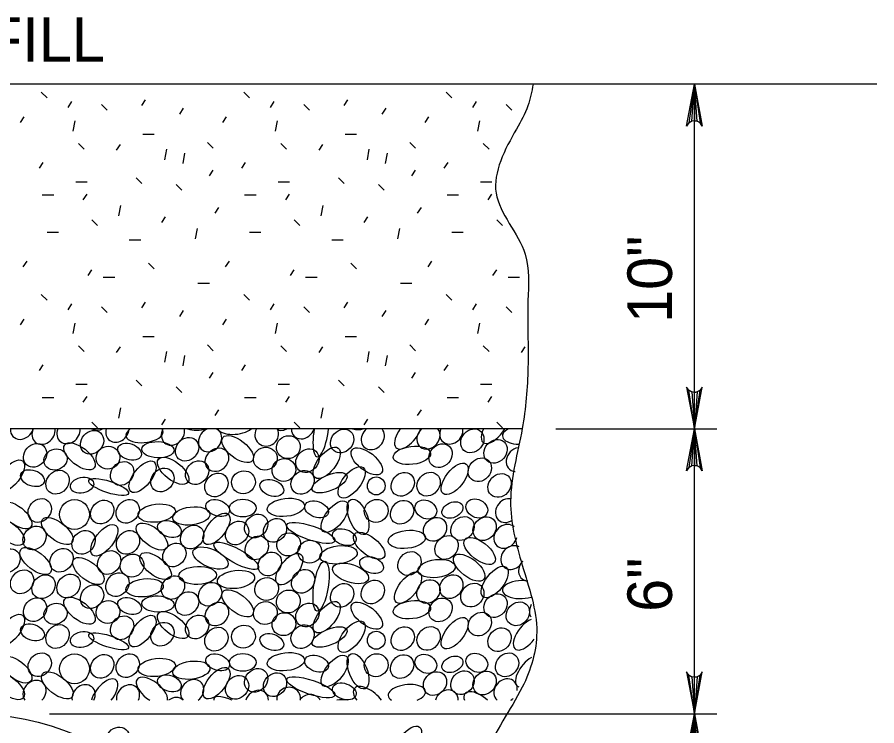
# Model space of a CAD drawing. Extents: x 1.32 to 7.47, y -3.56 to 5.14.
# Drawn here: x 3.909 to 5.068, y 0.019 to 0.974 of the extents above; entities that cross this region are included whole.
import ezdxf

# ---------------------------------------------------------------- set-up
doc = ezdxf.new("R2010")
doc.units = 0
for name, color, linetype in [('DETL-DIMS', 7, 'Continuous'), ('DETL-LINE', 7, 'Continuous'), ('DETL-NOTE', 7, 'Continuous'), ('DETL-PATT', 7, 'Continuous')]:
    doc.layers.add(name, color=color, linetype=linetype)

msp = doc.modelspace()

# ---------------------------------------------------------------- linework, layer by layer
at = {"layer": 'DETL-DIMS'}
for p, q in [((4.8221, 0.4194), (4.8221, 0.8841)), ((4.6354, 0.4194), (4.8524, 0.4194)), ((4.8221, 0.0356), (4.8221, 0.4194)), ((3.9532, 0.0356), (4.8524, 0.0356)), ((4.8221, -0.6917), (4.8221, 0.0356))]:
    msp.add_line(p, q, dxfattribs=at)
for points in [[(4.8221, 0.8841), (4.8327, 0.8276), (4.8297, 0.832), (4.8259, 0.8342), (4.8221, 0.8349), (4.8184, 0.8342), (4.8146, 0.832), (4.8116, 0.8276), (4.8221, 0.8841), (4.8146, 0.832), (4.8184, 0.8342), (4.8221, 0.8841), (4.8221, 0.8349), (4.8259, 0.8342), (4.8221, 0.8841), (4.8297, 0.832)], [(4.8221, 0.4194), (4.8327, 0.4759), (4.8297, 0.4716), (4.8259, 0.4693), (4.8221, 0.4687), (4.8184, 0.4693), (4.8146, 0.4716), (4.8116, 0.4759), (4.8221, 0.4194), (4.8146, 0.4716), (4.8184, 0.4693), (4.8221, 0.4194), (4.8221, 0.4687), (4.8259, 0.4693), (4.8221, 0.4194), (4.8297, 0.4716)], [(4.8221, 0.4194), (4.8327, 0.363), (4.8297, 0.3673), (4.8259, 0.3696), (4.8221, 0.3702), (4.8184, 0.3696), (4.8146, 0.3673), (4.8116, 0.363), (4.8221, 0.4194), (4.8146, 0.3673), (4.8184, 0.3696), (4.8221, 0.4194), (4.8221, 0.3702), (4.8259, 0.3696), (4.8221, 0.4194), (4.8297, 0.3673)], [(4.8221, 0.0356), (4.8327, 0.0921), (4.8297, 0.0877), (4.8259, 0.0855), (4.8221, 0.0849), (4.8184, 0.0855), (4.8146, 0.0877), (4.8116, 0.0921), (4.8221, 0.0356), (4.8146, 0.0877), (4.8184, 0.0855), (4.8221, 0.0356), (4.8221, 0.0849), (4.8259, 0.0855), (4.8221, 0.0356), (4.8297, 0.0877)], [(4.8221, 0.0356), (4.8327, -0.0209), (4.8297, -0.0165), (4.8259, -0.0143), (4.8221, -0.0136), (4.8184, -0.0143), (4.8146, -0.0165), (4.8116, -0.0209), (4.8221, 0.0356), (4.8146, -0.0165), (4.8184, -0.0143), (4.8221, 0.0356), (4.8221, -0.0136), (4.8259, -0.0143), (4.8221, 0.0356), (4.8297, -0.0165)]]:
    msp.add_lwpolyline(points, dxfattribs=at)
at = {"layer": 'DETL-LINE'}
for p, q in [((5.0678, 0.8841), (2.3812, 0.8841)), ((4.59, 0.4194), (3.0905, 0.4194))]:
    msp.add_line(p, q, dxfattribs=at)
msp.add_circle((3.8471, -0.328), 0.3636, dxfattribs=at)
msp.add_spline([(4.6047, 0.8841), (4.5978, 0.8549), (4.5822, 0.8236), (4.5548, 0.7374), (4.5939, 0.6551), (4.5978, 0.5924), (4.5978, 0.5022), (4.59, 0.4199), (4.5744, 0.322), (4.59, 0.2357), (4.6096, 0.1456), (4.59, 0.0712), (4.543, -0.019), (4.5665, -0.1679), (4.5783, -0.2463), (4.5509, -0.3207), (4.5626, -0.4069), (4.6057, -0.5167), (4.5978, -0.599), (4.5704, -0.6812), (4.5626, -0.7518), (4.59, -0.8615), (4.5822, -0.8733), (4.5744, -0.9341)], degree=3, dxfattribs=at)
at = {"layer": 'DETL-PATT'}
for p, q in [((3.942, 0.8734), (3.9497, 0.8657)), ((4.2148, 0.8734), (4.2225, 0.8657)), ((4.4875, 0.8734), (4.4952, 0.8657)), ((3.978, 0.8529), (3.9831, 0.8606)), ((4.0773, 0.8555), (4.0825, 0.8632)), ((4.2507, 0.8529), (4.2559, 0.8606)), ((4.3501, 0.8555), (4.3552, 0.8632)), ((4.5235, 0.8529), (4.5286, 0.8606)), ((4.0229, 0.8568), (4.0306, 0.8491)), ((4.1287, 0.8439), (4.1338, 0.8516)), ((4.2957, 0.8568), (4.3034, 0.8491)), ((4.4014, 0.8439), (4.4066, 0.8516)), ((4.5684, 0.8568), (4.5761, 0.8491)), ((3.9138, 0.8324), (3.9189, 0.8401)), ((3.987, 0.8349), (3.9844, 0.8208)), ((4.1865, 0.8324), (4.1916, 0.8401)), ((4.2597, 0.8349), (4.2571, 0.8208)), ((4.4592, 0.8324), (4.4644, 0.8401)), ((4.5324, 0.8349), (4.5299, 0.8208)), ((4.0786, 0.8169), (4.094, 0.8169)), ((4.3514, 0.8169), (4.3668, 0.8169)), ((3.9921, 0.8041), (3.9998, 0.7964)), ((4.0435, 0.7951), (4.0486, 0.8028)), ((4.166, 0.8054), (4.1737, 0.7977)), ((4.2648, 0.8041), (4.2726, 0.7964)), ((4.3162, 0.7951), (4.3214, 0.8028)), ((4.4387, 0.8054), (4.4464, 0.7977)), ((4.5376, 0.8041), (4.5453, 0.7964)), ((4.1107, 0.7964), (4.1082, 0.7823)), ((4.1351, 0.7913), (4.1326, 0.7771)), ((4.3835, 0.7964), (4.3809, 0.7823)), ((4.4079, 0.7913), (4.4053, 0.7771)), ((3.9395, 0.7707), (3.9446, 0.7784)), ((4.2122, 0.7707), (4.2173, 0.7784)), ((4.4849, 0.7707), (4.4901, 0.7784)), ((4.1685, 0.7604), (4.1737, 0.7682)), ((4.4413, 0.7604), (4.4464, 0.7682)), ((4.0696, 0.7579), (4.0773, 0.7502)), ((4.3424, 0.7579), (4.3501, 0.7502)), ((3.9883, 0.7527), (4.0037, 0.7527)), ((4.1236, 0.7489), (4.1313, 0.7412)), ((4.261, 0.7527), (4.2764, 0.7527)), ((4.3963, 0.7489), (4.404, 0.7412)), ((4.5337, 0.7527), (4.5491, 0.7527)), ((3.9433, 0.7348), (3.9587, 0.7348)), ((3.9985, 0.7283), (4.0037, 0.736)), ((4.216, 0.7348), (4.2315, 0.7348)), ((4.2713, 0.7283), (4.2764, 0.736)), ((4.4888, 0.7348), (4.5042, 0.7348)), ((4.544, 0.7283), (4.5491, 0.736)), ((4.0486, 0.7206), (4.0461, 0.7065)), ((4.3214, 0.7206), (4.3188, 0.7065)), ((4.1762, 0.7103), (4.1814, 0.7181)), ((4.449, 0.7103), (4.4541, 0.7181)), ((4.0101, 0.7014), (4.0178, 0.6937)), ((4.1043, 0.6975), (4.1095, 0.7052)), ((4.2828, 0.7014), (4.2905, 0.6937)), ((4.377, 0.6975), (4.3822, 0.7052)), ((4.5556, 0.7014), (4.5633, 0.6937)), ((3.9497, 0.6847), (3.9651, 0.6847)), ((4.1518, 0.6898), (4.1493, 0.6757)), ((4.2225, 0.6847), (4.2379, 0.6847)), ((4.4246, 0.6898), (4.422, 0.6757)), ((4.4952, 0.6847), (4.5106, 0.6847)), ((4.0606, 0.6744), (4.0761, 0.6744)), ((4.3334, 0.6744), (4.3488, 0.6744)), ((3.9176, 0.638), (3.9228, 0.6457)), ((4.0863, 0.6431), (4.094, 0.6354)), ((4.1904, 0.638), (4.1955, 0.6457)), ((4.3591, 0.6431), (4.3668, 0.6354)), ((4.4631, 0.638), (4.4682, 0.6457)), ((4.005, 0.6264), (4.0101, 0.6341)), ((4.2777, 0.6264), (4.2828, 0.6341)), ((4.5504, 0.6264), (4.5556, 0.6341)), ((4.0255, 0.6238), (4.0409, 0.6238)), ((4.1531, 0.6161), (4.1685, 0.6161)), ((4.2982, 0.6238), (4.3136, 0.6238)), ((4.4258, 0.6161), (4.4413, 0.6161)), ((4.571, 0.6238), (4.5864, 0.6238)), ((3.942, 0.6007), (3.9497, 0.593)), ((4.2148, 0.6007), (4.2225, 0.593)), ((4.4875, 0.6007), (4.4952, 0.593)), ((3.978, 0.5802), (3.9831, 0.5879)), ((4.0229, 0.584), (4.0306, 0.5763)), ((4.0773, 0.5827), (4.0825, 0.5905)), ((4.2507, 0.5802), (4.2559, 0.5879)), ((4.2957, 0.584), (4.3034, 0.5763)), ((4.3501, 0.5827), (4.3552, 0.5905)), ((4.5235, 0.5802), (4.5286, 0.5879)), ((4.5684, 0.584), (4.5761, 0.5763)), ((4.1287, 0.5712), (4.1338, 0.5789)), ((4.4014, 0.5712), (4.4066, 0.5789)), ((3.9138, 0.5596), (3.9189, 0.5673)), ((3.987, 0.5622), (3.9844, 0.5481)), ((4.1865, 0.5596), (4.1916, 0.5673)), ((4.2597, 0.5622), (4.2571, 0.5481)), ((4.4592, 0.5596), (4.4644, 0.5673)), ((4.5324, 0.5622), (4.5299, 0.5481)), ((4.0786, 0.5442), (4.094, 0.5442)), ((4.3514, 0.5442), (4.3668, 0.5442)), ((3.9921, 0.5314), (3.9998, 0.5237)), ((4.0435, 0.5224), (4.0486, 0.5301)), ((4.1107, 0.5237), (4.1082, 0.5095)), ((4.166, 0.5327), (4.1737, 0.5249)), ((4.2648, 0.5314), (4.2726, 0.5237)), ((4.3162, 0.5224), (4.3214, 0.5301)), ((4.3835, 0.5237), (4.3809, 0.5095)), ((4.4387, 0.5327), (4.4464, 0.5249)), ((4.5376, 0.5314), (4.5453, 0.5237)), ((4.589, 0.5224), (4.5941, 0.5301)), ((4.1351, 0.5185), (4.1326, 0.5044)), ((4.4079, 0.5185), (4.4053, 0.5044)), ((3.9395, 0.498), (3.9446, 0.5057)), ((4.2122, 0.498), (4.2173, 0.5057)), ((4.4849, 0.498), (4.4901, 0.5057)), ((4.1685, 0.4877), (4.1737, 0.4954)), ((4.4413, 0.4877), (4.4464, 0.4954)), ((3.9883, 0.48), (4.0037, 0.48)), ((4.0696, 0.4851), (4.0773, 0.4774)), ((4.1236, 0.4762), (4.1313, 0.4684)), ((4.261, 0.48), (4.2764, 0.48)), ((4.3424, 0.4851), (4.3501, 0.4774)), ((4.3963, 0.4762), (4.404, 0.4684)), ((4.5337, 0.48), (4.5491, 0.48)), ((3.9433, 0.462), (3.9587, 0.462)), ((3.9985, 0.4556), (4.0037, 0.4633)), ((4.216, 0.462), (4.2315, 0.462)), ((4.2713, 0.4556), (4.2764, 0.4633)), ((4.4888, 0.462), (4.5042, 0.462)), ((4.544, 0.4556), (4.5491, 0.4633)), ((4.0486, 0.4479), (4.0461, 0.4338)), ((4.1762, 0.4376), (4.1814, 0.4453)), ((4.3214, 0.4479), (4.3188, 0.4338)), ((4.449, 0.4376), (4.4541, 0.4453)), ((4.0101, 0.4286), (4.0178, 0.4209)), ((4.1043, 0.4248), (4.1095, 0.4325)), ((4.2828, 0.4286), (4.2905, 0.4209)), ((4.377, 0.4248), (4.3822, 0.4325)), ((4.5556, 0.4286), (4.5633, 0.4209))]:
    msp.add_line(p, q, dxfattribs=at)
for centre in [(3.9868, 0.3041), (3.9868, 0.0961)]:
    msp.add_circle(centre, 0.0201, dxfattribs=at)
for centre, major_axis, ratio, start_param, end_param in [((3.916, 0.4214), (0.0114, 0.0128), 0.844245, 2.337239, 5.2336), ((3.945, 0.4148), (0.0114, 0.0128), 0.844245, 1.920061, 5.650779), ((3.9787, 0.4157), (0.0114, 0.0128), 0.844245, 1.977863, 5.592976), ((4.0054, 0.4359), (-0.0199, 0.0156), 0.479042, 2.140528, 3.0476), ((4.0446, 0.4176), (0.0114, 0.0128), 0.844245, 2.101903, 5.468936), ((4.0811, 0.4133), (-0.0251, -0.003), 0.479042, 5.523456, 9.693542), ((4.1194, 0.4136), (0.0114, 0.0128), 0.844245, 1.843624, 5.727215), ((4.1527, 0.43), (-0.0253, -0.0008), 0.479042, 0.985107, 2.022292), ((4.1694, 0.4047), (0.0114, 0.0128), 0.844245, 1.036345, 6.534494), ((4.2043, 0.4245), (-0.0251, -0.003), 0.479042, 0.177054, 2.473573), ((4.2457, 0.4118), (0.015, 0.006), 0.948581, 2.223153, 6.403606), ((4.2762, 0.4384), (-0.0156, -0.0199), 0.479042, 6.174501, 7.111824), ((4.2947, 0.4221), (0.0114, 0.0128), 0.844245, 2.382235, 5.188604), ((4.3189, 0.4156), (0.0052, 0.0337), 0.282192, 1.499195, 4.870192), ((4.3587, 0.4326), (-0.024, 0.0079), 0.479042, 1.837904, 2.504279), ((4.3887, 0.4076), (0.0114, 0.0128), 0.844245, 1.383909, 6.18693), ((4.4362, 0.4136), (-0.0156, -0.0199), 0.479042, 4.793971, 8.492354), ((4.4636, 0.4083), (0.0114, 0.0128), 0.844245, 1.442961, 6.127878), ((4.4945, 0.415), (0.0114, 0.0128), 0.844245, 1.933643, 5.637196), ((4.553, 0.4211), (-0.0156, -0.0199), 0.479042, 5.151093, 8.135232), ((4.5887, 0.4109), (-0.0253, -0.0008), 0.479042, 5.437186, 7.710822), ((4.5841, 0.3782), (0.0114, 0.0128), 0.844245, 0.789884, 3.730487), ((4.5696, 0.3094), (0.0114, 0.0128), 0.844245, 0.446616, 4.424977), ((4.5676, 0.2747), (0.0114, 0.0128), 0.844245, 6.263167, 11.550365), ((4.5768, 0.2461), (0.0114, 0.0128), 0.844245, 0.181002, 5.06616), ((4.6007, 0.2307), (0.0114, 0.0128), 0.844245, 1.485719, 3.761443), ((4.5887, 0.2029), (-0.0253, -0.0008), 0.479042, 4.32869, 8.397006), ((4.6179, 0.1858), (-0.0156, -0.0199), 0.479042, 5.210525, 6.260787), ((4.5962, 0.1427), (-0.0156, -0.0199), 0.479042, 3.841705, 7.893613), ((4.5992, 0.0926), (-0.0156, -0.0199), 0.479042, 3.986958, 6.45917), ((3.9329, 0.0645), (0.0114, 0.0128), 0.844245, 4.624083, 9.229941), ((4.0269, 0.0614), (-0.0156, -0.0199), 0.479042, 1.564537, 5.438603), ((4.0911, 0.0665), (-0.0199, 0.0156), 0.479042, 3.399625, 8.071688), ((4.1452, 0.0657), (0.0114, 0.0128), 0.844245, 4.512207, 9.341818), ((4.5676, 0.0667), (0.0114, 0.0128), 0.844245, 5.372018, 9.43564), ((3.9989, 0.0587), (0.0114, 0.0128), 0.844245, 5.042086, 8.811939), ((4.0588, 0.0586), (0.0114, 0.0128), 0.844245, 5.05265, 8.801375), ((4.2753, 0.0558), (0.015, 0.006), 0.948581, 5.750872, 9.159072), ((4.3837, 0.054), (-0.0199, 0.0156), 0.479042, 4.150915, 7.320397), ((4.4345, 0.0627), (-0.0251, -0.003), 0.479042, 2.09792, 6.835893), ((4.1213, 0.0415), (0.0114, 0.0128), 0.844245, 6.230995, 7.623029), ((4.2046, 0.0404), (0.0299, -0.0164), 0.282192, 1.905311, 3.425677), ((4.2324, 0.0512), (0.0114, 0.0128), 0.844245, 5.517807, 8.336218), ((4.3038, 0.0461), (0.015, 0.006), 0.948581, 0.126488, 2.217085), ((4.488, 0.0517), (0.0114, 0.0128), 0.844245, 5.487764, 8.36626), ((4.5326, 0.047), (-0.0199, 0.0156), 0.479042, 4.542489, 6.928824), ((4.3426, 0.0419), (-0.0251, -0.003), 0.479042, 4.187228, 4.746585), ((4.5676, 0.0667), (0.0114, 0.0128), 0.844245, 4.418385, 4.670773), ((4.5768, 0.0382), (0.0114, 0.0128), 0.844245, 0.836346, 0.862965)]:
    msp.add_ellipse(centre, major_axis=major_axis, ratio=ratio, start_param=start_param, end_param=end_param, dxfattribs=at)
for centre, major_axis, ratio in [((4.0104, 0.4013), (0.0114, 0.0128), 0.844245), ((4.3474, 0.4031), (0.0114, 0.0128), 0.844245), ((4.5228, 0.4034), (0.0114, 0.0128), 0.844245), ((4.1384, 0.3921), (0.0114, 0.0128), 0.844245), ((4.2066, 0.3923), (-0.0199, 0.0156), 0.479042), ((4.2748, 0.3949), (0.015, 0.006), 0.948581), ((4.5541, 0.3892), (0.0114, 0.0128), 0.844245), ((3.9336, 0.3839), (0.0114, 0.0128), 0.844245), ((3.9612, 0.3783), (-0.0148, -0.0059), 0.87402), ((3.9935, 0.3825), (-0.0199, 0.0156), 0.479042), ((4.0318, 0.3807), (0.015, 0.006), 0.948581), ((4.0609, 0.3887), (0.0156, -0.0055), 0.646802), ((4.0991, 0.3914), (0.0217, -0.0009), 0.504072), ((4.1787, 0.3779), (0.0114, 0.0128), 0.844245), ((4.2439, 0.3793), (0.015, 0.006), 0.948581), ((4.3005, 0.3767), (0.0114, 0.0128), 0.844245), ((4.3266, 0.3737), (-0.0156, -0.0199), 0.479042), ((4.3806, 0.3757), (-0.0199, 0.0156), 0.479042), ((4.4414, 0.3838), (-0.0251, -0.003), 0.479042), ((4.48, 0.3835), (0.0114, 0.0128), 0.844245), ((4.1196, 0.363), (-0.0199, 0.0156), 0.479042), ((4.5329, 0.3644), (0.0114, 0.0128), 0.844245), ((3.9011, 0.3564), (-0.0156, -0.0199), 0.479042), ((4.0509, 0.3594), (0.0114, 0.0128), 0.844245), ((4.0784, 0.355), (-0.0156, -0.0199), 0.479042), ((4.1519, 0.3606), (0.0114, 0.0128), 0.844245), ((4.2689, 0.3642), (0.015, 0.006), 0.948581), ((4.3601, 0.3474), (-0.0156, -0.0199), 0.479042), ((4.4991, 0.3522), (-0.0156, -0.0199), 0.479042), ((3.9301, 0.3531), (0.0156, -0.0055), 0.646802), ((3.9639, 0.3477), (0.0114, 0.0128), 0.844245), ((4.1051, 0.3507), (0.0114, 0.0128), 0.844245), ((4.1779, 0.344), (0.0114, 0.0128), 0.844245), ((4.2144, 0.3476), (0.015, 0.006), 0.948581), ((4.2941, 0.3474), (0.0114, 0.0128), 0.844245), ((4.3304, 0.347), (-0.0232, -0.0098), 0.422273), ((4.429, 0.3449), (0.0114, 0.0128), 0.844245), ((4.4639, 0.345), (0.0114, 0.0128), 0.844245), ((4.5595, 0.3433), (0.0114, 0.0128), 0.844245), ((3.9969, 0.3436), (-0.0156, -0.0031), 0.666084), ((4.0327, 0.3412), (-0.0268, 0.0086), 0.276285), ((4.2526, 0.34), (0.0156, -0.0055), 0.646802), ((4.3933, 0.3427), (0, 0.0121), 0.982495), ((3.9398, 0.3095), (0.0114, 0.0128), 0.844245), ((4.0241, 0.3074), (0.0114, 0.0128), 0.844245), ((4.0584, 0.3084), (0.0114, 0.0128), 0.844245), ((4.1796, 0.3127), (0.0156, -0.0055), 0.646802), ((4.2135, 0.3128), (0.0178, 0), 0.671766), ((4.2716, 0.3137), (-0.0251, -0.003), 0.479042), ((4.3374, 0.3013), (-0.0156, -0.0199), 0.479042), ((4.3689, 0.3009), (0.0094, -0.0235), 0.479042), ((4.3933, 0.309), (0.015, 0.006), 0.948581), ((4.4281, 0.3072), (0.0114, 0.0128), 0.844245), ((4.4602, 0.3109), (0.0136, -0.007), 0.796199), ((4.5289, 0.3123), (0.0136, -0.007), 0.796199), ((3.9081, 0.3031), (-0.0199, 0.0156), 0.479042), ((4.0975, 0.306), (-0.0251, -0.003), 0.479042), ((4.1441, 0.3022), (-0.0251, -0.003), 0.479042), ((4.313, 0.3111), (0.0156, -0.0055), 0.646802), ((4.496, 0.3102), (-0.0136, -0.0061), 0.687276), ((3.8981, 0.2808), (-0.0199, 0.0156), 0.479042), ((3.9636, 0.2818), (-0.0199, 0.0156), 0.479042), ((4.1781, 0.2848), (-0.0156, -0.0199), 0.479042), ((4.2315, 0.2886), (0.0114, 0.0128), 0.844245), ((4.4725, 0.2842), (0.0114, 0.0128), 0.844245), ((4.5095, 0.2853), (0.0114, 0.0128), 0.844245), ((4.5394, 0.2851), (0.0114, 0.0128), 0.844245), ((3.9329, 0.2725), (0.0114, 0.0128), 0.844245), ((4.0269, 0.2694), (-0.0156, -0.0199), 0.479042), ((4.0911, 0.2744), (-0.0199, 0.0156), 0.479042), ((4.1146, 0.2844), (0.0156, -0.0055), 0.646802), ((4.1452, 0.2737), (0.0114, 0.0128), 0.844245), ((4.2058, 0.2792), (0.0114, 0.0128), 0.844245), ((4.2569, 0.2828), (0.0114, 0.0128), 0.844245), ((4.3051, 0.2793), (0.0323, -0.0109), 0.282192), ((3.9989, 0.2667), (0.0114, 0.0128), 0.844245), ((4.0588, 0.2665), (0.0114, 0.0128), 0.844245), ((4.2753, 0.2638), (0.015, 0.006), 0.948581), ((4.3503, 0.2736), (0.0156, -0.0055), 0.646802), ((4.3837, 0.262), (-0.0199, 0.0156), 0.479042), ((4.4345, 0.2706), (-0.0251, -0.003), 0.479042), ((4.1213, 0.2495), (0.0114, 0.0128), 0.844245), ((4.2046, 0.2484), (0.0299, -0.0164), 0.282192), ((4.2324, 0.2592), (0.0114, 0.0128), 0.844245), ((4.3038, 0.254), (0.015, 0.006), 0.948581), ((4.488, 0.2597), (0.0114, 0.0128), 0.844245), ((4.5326, 0.255), (-0.0199, 0.0156), 0.479042), ((3.8977, 0.242), (0.0114, 0.0128), 0.844245), ((3.9344, 0.2414), (-0.0199, 0.0156), 0.479042), ((3.9692, 0.2425), (0.0114, 0.0128), 0.844245), ((4.0334, 0.2394), (0.0114, 0.0128), 0.844245), ((4.096, 0.2346), (-0.0199, 0.0156), 0.479042), ((4.1701, 0.2454), (-0.0233, 0.01), 0.479042), ((4.2499, 0.2375), (0.0114, 0.0128), 0.844245), ((4.3426, 0.2498), (-0.0251, -0.003), 0.479042), ((4.4381, 0.2381), (0.0114, 0.0128), 0.844245), ((4.0054, 0.2279), (-0.0199, 0.0156), 0.479042), ((4.0643, 0.2353), (0.015, 0.006), 0.948581), ((4.2762, 0.2305), (-0.0156, -0.0199), 0.479042), ((4.387, 0.236), (0.0156, -0.0055), 0.646802), ((4.4746, 0.2313), (-0.0251, -0.003), 0.479042), ((4.5186, 0.2324), (-0.0199, 0.0156), 0.479042), ((4.1527, 0.222), (-0.0253, -0.0008), 0.479042), ((4.2947, 0.2141), (0.0114, 0.0128), 0.844245), ((4.3189, 0.2076), (0.0052, 0.0337), 0.282192), ((4.3587, 0.2247), (-0.024, 0.0079), 0.479042), ((4.553, 0.2132), (-0.0156, -0.0199), 0.479042), ((3.916, 0.2134), (0.0114, 0.0128), 0.844245), ((3.945, 0.2068), (0.0114, 0.0128), 0.844245), ((3.9787, 0.2077), (0.0114, 0.0128), 0.844245), ((4.0446, 0.2097), (0.0114, 0.0128), 0.844245), ((4.1194, 0.2057), (0.0114, 0.0128), 0.844245), ((4.2043, 0.2166), (-0.0251, -0.003), 0.479042), ((4.2457, 0.2038), (0.015, 0.006), 0.948581), ((4.4362, 0.2056), (-0.0156, -0.0199), 0.479042), ((4.4945, 0.207), (0.0114, 0.0128), 0.844245), ((4.0104, 0.1933), (0.0114, 0.0128), 0.844245), ((4.0811, 0.2054), (-0.0251, -0.003), 0.479042), ((4.1694, 0.1967), (0.0114, 0.0128), 0.844245), ((4.3474, 0.1951), (0.0114, 0.0128), 0.844245), ((4.3887, 0.1997), (0.0114, 0.0128), 0.844245), ((4.4636, 0.2003), (0.0114, 0.0128), 0.844245), ((4.5228, 0.1955), (0.0114, 0.0128), 0.844245), ((4.1384, 0.1841), (0.0114, 0.0128), 0.844245), ((4.2066, 0.1844), (-0.0199, 0.0156), 0.479042), ((4.2748, 0.1869), (0.015, 0.006), 0.948581), ((4.5541, 0.1812), (0.0114, 0.0128), 0.844245), ((3.9336, 0.1759), (0.0114, 0.0128), 0.844245), ((3.9612, 0.1703), (-0.0148, -0.0059), 0.87402), ((3.9935, 0.1745), (-0.0199, 0.0156), 0.479042), ((4.0318, 0.1727), (0.015, 0.006), 0.948581), ((4.0609, 0.1807), (0.0156, -0.0055), 0.646802), ((4.0991, 0.1834), (0.0217, -0.0009), 0.504072), ((4.1787, 0.1699), (0.0114, 0.0128), 0.844245), ((4.2439, 0.1713), (0.015, 0.006), 0.948581), ((4.3005, 0.1688), (0.0114, 0.0128), 0.844245), ((4.3266, 0.1657), (-0.0156, -0.0199), 0.479042), ((4.3806, 0.1677), (-0.0199, 0.0156), 0.479042), ((4.4414, 0.1758), (-0.0251, -0.003), 0.479042), ((4.48, 0.1756), (0.0114, 0.0128), 0.844245), ((4.5841, 0.1703), (0.0114, 0.0128), 0.844245), ((4.1196, 0.1551), (-0.0199, 0.0156), 0.479042), ((4.2689, 0.1563), (0.015, 0.006), 0.948581), ((4.5329, 0.1564), (0.0114, 0.0128), 0.844245), ((3.9011, 0.1484), (-0.0156, -0.0199), 0.479042), ((4.0509, 0.1514), (0.0114, 0.0128), 0.844245), ((4.0784, 0.147), (-0.0156, -0.0199), 0.479042), ((4.1519, 0.1526), (0.0114, 0.0128), 0.844245), ((4.3601, 0.1394), (-0.0156, -0.0199), 0.479042), ((4.4991, 0.1442), (-0.0156, -0.0199), 0.479042), ((3.9301, 0.1452), (0.0156, -0.0055), 0.646802), ((3.9639, 0.1397), (0.0114, 0.0128), 0.844245), ((4.1051, 0.1428), (0.0114, 0.0128), 0.844245), ((4.1779, 0.1361), (0.0114, 0.0128), 0.844245), ((4.2144, 0.1396), (0.015, 0.006), 0.948581), ((4.2941, 0.1395), (0.0114, 0.0128), 0.844245), ((4.3304, 0.139), (-0.0232, -0.0098), 0.422273), ((4.429, 0.1369), (0.0114, 0.0128), 0.844245), ((4.4639, 0.1371), (0.0114, 0.0128), 0.844245), ((4.5595, 0.1354), (0.0114, 0.0128), 0.844245), ((3.9969, 0.1356), (-0.0156, -0.0031), 0.666084), ((4.0327, 0.1332), (-0.0268, 0.0086), 0.276285), ((4.2526, 0.1321), (0.0156, -0.0055), 0.646802), ((4.3933, 0.1347), (0, 0.0121), 0.982495), ((3.9081, 0.0952), (-0.0199, 0.0156), 0.479042), ((3.9398, 0.1016), (0.0114, 0.0128), 0.844245), ((4.0241, 0.0994), (0.0114, 0.0128), 0.844245), ((4.0584, 0.1004), (0.0114, 0.0128), 0.844245), ((4.1796, 0.1047), (0.0156, -0.0055), 0.646802), ((4.2135, 0.1048), (0.0178, 0), 0.671766), ((4.2716, 0.1057), (-0.0251, -0.003), 0.479042), ((4.313, 0.1032), (0.0156, -0.0055), 0.646802), ((4.3374, 0.0933), (-0.0156, -0.0199), 0.479042), ((4.3689, 0.0929), (0.0094, -0.0235), 0.479042), ((4.3933, 0.101), (0.015, 0.006), 0.948581), ((4.4281, 0.0992), (0.0114, 0.0128), 0.844245), ((4.4602, 0.1029), (0.0136, -0.007), 0.796199), ((4.5289, 0.1043), (0.0136, -0.007), 0.796199), ((4.5696, 0.1015), (0.0114, 0.0128), 0.844245), ((4.0975, 0.098), (-0.0251, -0.003), 0.479042), ((4.1441, 0.0943), (-0.0251, -0.003), 0.479042), ((4.496, 0.1022), (-0.0136, -0.0061), 0.687276), ((3.8981, 0.0728), (-0.0199, 0.0156), 0.479042), ((3.9636, 0.0739), (-0.0199, 0.0156), 0.479042), ((4.1781, 0.0768), (-0.0156, -0.0199), 0.479042), ((4.2315, 0.0806), (0.0114, 0.0128), 0.844245), ((4.2569, 0.0748), (0.0114, 0.0128), 0.844245), ((4.4725, 0.0763), (0.0114, 0.0128), 0.844245), ((4.5095, 0.0774), (0.0114, 0.0128), 0.844245), ((4.5394, 0.0771), (0.0114, 0.0128), 0.844245), ((4.1146, 0.0764), (0.0156, -0.0055), 0.646802), ((4.2058, 0.0712), (0.0114, 0.0128), 0.844245), ((4.3051, 0.0713), (0.0323, -0.0109), 0.282192), ((4.3503, 0.0656), (0.0156, -0.0055), 0.646802), ((4.0446, 0.0017), (0.0114, 0.0128), 0.844245), ((4.4362, -0.0023), (-0.0156, -0.0199), 0.479042)]:
    msp.add_ellipse(centre, major_axis=major_axis, ratio=ratio, dxfattribs=at)

# ---------------------------------------------------------------- texts
at = {"layer": 'DETL-NOTE'}
msp.add_text('EARTH FILL', height=0.06, dxfattribs=at).set_placement((3.573, 0.9144))
for s, p in [('10"', (4.7918, 0.5622)), ('6"', (4.7918, 0.1729))]:
    msp.add_text(s, height=0.06, rotation=90, dxfattribs=at).set_placement(p)

doc.saveas('drawing.dxf')
